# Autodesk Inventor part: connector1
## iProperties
Shininess: 64.0
Length Units: 11269
Angle Units: 11279
Time Units: 11290
Mass Units: 11283
Length Display Precision: 3
Angle Display Precision: 2
Compacted: True
Part Number: connector1
Document SubType Name: Modeling
Created: 2003-07
Designer: John Blackburn
Density: 0.0
Volumn: 0.0
Area: 0.0
PropertySet Name: Model Information
Control State: 0
Master: False
Checked Out: False
Author: John Blackburn
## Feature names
1. Extrusion1
2. Extrusion2
3. Extrusion3
4. Rectangular Pattern1
5. Fillet2
